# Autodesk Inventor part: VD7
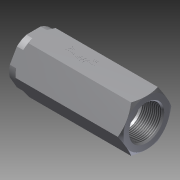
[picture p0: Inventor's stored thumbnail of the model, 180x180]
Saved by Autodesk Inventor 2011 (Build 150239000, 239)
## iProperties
Created: 2012-01
Part Number: VD7
Document SubType Name: Modeling
Designer: khramov
Density: 1 g/cm^3
Author: khramov
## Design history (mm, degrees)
derived "VD7_W1_30.ipt"
feature "Твердое тело1::VD7_W1_30.ipt" dims "d0" = 10
tag "Элемент создания маркировки1"
node "Твердое тело1"
